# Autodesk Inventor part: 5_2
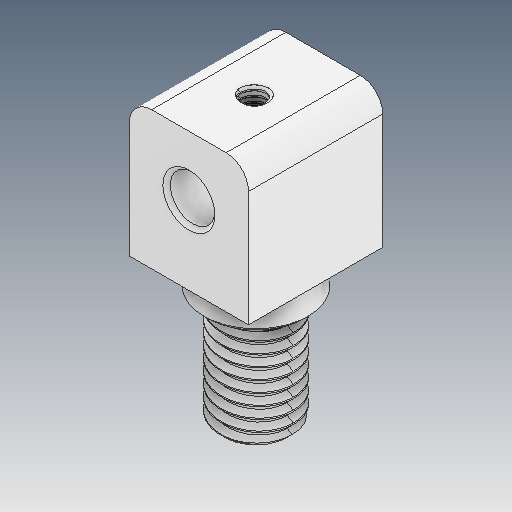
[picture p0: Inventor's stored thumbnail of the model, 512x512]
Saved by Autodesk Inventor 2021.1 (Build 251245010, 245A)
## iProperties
Created: 2021-06
Part Number: 5_2
Material: Ogólny
Document SubType Name: Modeling
Designer: user
Density: 1 g/cm^3
Appearance: Domyślna
Author: user
Revision Number: ÈÎºÎ
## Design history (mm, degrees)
feature "ÊäÈë1"
node "Bryła1"
